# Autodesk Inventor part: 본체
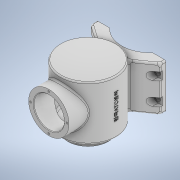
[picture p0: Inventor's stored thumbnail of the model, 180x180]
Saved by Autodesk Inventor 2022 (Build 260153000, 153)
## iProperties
Created: 2023-04
Part Number: 본체
Material: 일반
Document SubType Name: Modeling
Designer: Admin
Density: 1 g/cm^3
Appearance: 기본값
Author: Admin
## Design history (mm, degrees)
sketch "스케치1"
  geometry: L1 (-62, 40)-(62, 40); L2 (62, 40)-(62, -40); L3 (62, -40)-(-62, -40); L4 (-62, -40)-(-62, 40); L5 (-86.8, 0)-(86.8, 0) reference; L6 (0, -56)-(0, 56) reference; 1 further point
  constraints: 8 end point, 2 parallel, 1 horizontal, 1 perpendicular, 2 other
  dimensions: "d0" = 124 distance of L1.start L1.end; "d1" = 80 distance of L3.end L1.start
extrude "돌출1" new body sketch "스케치1" stored distance "d2" = 10; taper "d3" = 0 deg
sketch "스케치2"
  geometry: 1 further point
sketch "스케치3"
  geometry: L1 (40, -5)-(-40, -5) reference; L2 (-40, -5)-(-40, 5) reference; L3 (-133.479, 72)-(264.868, 72); L4 (-60, 72)-(-48, 72); L5 (-48, 72)-(-48, 108); L6 (-48, 108)-(-60, 108); L7 (-60, 108)-(-60, 72); L8 (-48, 72)-(-36, 72); L9 (-36, 122)-(-48, 122); L10 (-48, 122)-(-48, 72); L11 (-36, 72)-(36, 72); L12 (36, 72)-(48.336, 72); L13 (48.336, 72)-(48.336, 122); L14 (48.336, 122)-(36, 122); L15 (0, -30.534)-(0, 148.205) reference; L16 (-36, 122)-(36, 122); A1 r 113 centre (-53, 72) between (60, 72) and (48.336, 122); 3 further points
  constraints: 26 end point, 5 horizontal, 5 parallel, 3 point on line, 2 perpendicular, 2 point on circle, 1 centre point
  dimensions: "d16" = 113 radius of A1; "d17" = 20 distance from line of L2 L4.start; "d18" = 120 horizontal distance of L6.end A1.start; "d19" = 108 horizontal distance of A1.start L9.end; "d21" = 72 diameter of L6.end L3; "d22" = 100 diameter of L9.end L3; "d24" = 100 diameter of L13.end L3; "d28" = 154 diameter of L1 L3
revolve "회전1" sketch "스케치3" stored, may be unused: angle "d25" = 90 deg
node "작업 평면1"
sketch "스케치5"
  geometry: L1 (36, -60)-(-36, -60) reference; L2 (0, -84)-(0, 84) reference; C1 r 36 at (0, 2); 1 further point
  constraints: 1 centre point, 1 point on line
  dimensions: "d109" = 62 distance from line of L1 C1.centre; "d110" = 72 diameter of C1
extrude "돌출2" join sketch "스케치5" stored distance "d31" = 142; taper "d32" = 0 deg
sketch "스케치10"
  geometry: L1 (-85.453, 72)-(94.043, 72); L2 (-40, -5)-(40, -5) reference; L3 (-60, 36)-(-60, 108) reference; L4 (-60, 72)-(-41, 72); L5 (-41, 72)-(-41, 99); L6 (-41, 99)-(-60, 99); L7 (-60, 99)-(-60, 72); L8 (-41, 72)-(44.499, 72); L9 (44.499, 72)-(44.499, 115); L10 (44.499, 115)-(-41, 115); L11 (-41, 115)-(-41, 72); A1 r 113 centre (-53, 72) between (48.336, 22) and (48.336, 122) reference; A2 r 113 centre (-60, 72) between (53, 72) and (44.499, 115); 3 further points
  constraints: 18 end point, 4 parallel, 3 horizontal, 2 perpendicular, 2 point on circle, 2 point on line, 1 centre point, 1 midpoint
  dimensions: "d40" = 77 distance between parallel lines of L2 L1; "d42" = 54 diameter of L6.end L1; "d43" = 86 diameter of L10.end L1; "d45" = 19 distance of L5.end L6.end; "d48" = 226 diameter of A2; "d49" = 7 distance of A1.centre A2.centre
revolve "회전2" sketch "스케치10" stored, may be unused: angle "d50" = 90 deg
sketch "스케치22"
  geometry: C1 r 27 at (0, 0); C2 r 36 at (0, 0) reference; 1 further point
  constraints: 1 centre point, 1 coincident
  dimensions: "d112" = 54 diameter of C1
extrude "돌출8" cut sketch "스케치22" stored distance "d113" = 10; taper "d114" = 0 deg
sketch "스케치23"
  geometry: C1 r 27 at (0, 0) reference; C2 r 36 at (0, 0) reference; 5 further points
  constraints: 1 horizontal alignment, 5 other
  dimensions: "d115" = 32.5 distance of C1.centre point (-32.5, 0); "d118" = 360 deg dimension on C2.centre point (-32.5, 0) (derived)
hole "구멍4" sketch "스케치23" at (-32.5, 0), (0, -32.5), (32.5, 0), (0, 32.5) diameter "d120" = 3.242; stored, may be unused: countersink angle "d124" = 90 deg, drill point angle "d126" = 118 deg; dims "d121" = 8, "d122" = 4, "d123" = 2, "d125" = 10
sketch "스케치13"
  geometry: L1 (0, -102.4)-(0, 75.4) reference; C1 r 27 at (0, 0) reference; C2 r 36 at (0, 0) reference; 5 further points
  constraints: 1 point on line, 5 other
  dimensions: "d66" = 32.5 distance of C1.centre point (0, 32.5); "d69" = 360 deg dimension on C2.centre point (0, 32.5) (derived)
hole "구멍2" sketch "스케치13" at (0, 32.5), (-32.5, 0), (0, -32.5), (32.5, 0) diameter "d71" = 3.242; stored, may be unused: countersink angle "d75" = 90 deg, drill point angle "d77" = 118 deg; dims "d72" = 8, "d73" = 4, "d74" = 2, "d76" = 10
sketch "스케치14"
  geometry: L1 (62, 40)-(-62, 40) reference; L2 (-62, -40)-(62, -40) reference; L3 (-10, 40)-(10, 40); L4 (10, 40)-(10, -40); L5 (10, -40)-(-10, -40); L6 (-10, -40)-(-10, 40); L7 (0, -84)-(0, 84) reference; 1 further point
  constraints: 8 end point, 2 parallel, 2 point on line, 1 horizontal, 1 perpendicular, 1 other
  dimensions: "d78" = 20 distance between parallel lines of L6 L4
extrude "돌출5" join sketch "스케치14" stored distance "d79" = 10; taper "d80" = 0 deg
sketch "스케치15"
  geometry: L1 (-62, 5)-(-10, 5) reference; L2 (-62, 5)-(-26.694, 29.722); L3 (-62, -5)-(-62, 5) reference; 2 further points
  constraints: 2 end point, 2 other
  dimensions: "d81" = 55 deg angle of L3 L2
feature "리브1" sketch "스케치15" dims "d82" = 1, "d83" = 80, "d84" = 0, "d85" = 0, "d86" = 1, "d87" = 1
sketch "스케치16"
  geometry: L1 (124, 0)-(0, 0) reference; L2 (62, -12.727)-(62, 19.916); L3 (0, 10)-(0, 0) reference; L4 (62, 17)-(82.89, 17); L5 (23.5, 0)-(100.5, 0); A1 r 52.096 centre (62, -35.096) between (100.5, 0) and (23.5, 0); 1 further point
  constraints: 6 end point, 3 point on circle, 3 point on line, 1 centre point, 1 collinear, 1 horizontal, 1 symmetric about line, 1 tangent, 1 vertical
  dimensions: "d88" = 77 distance of L5.end L5.start; "d89" = 62 distance between parallel lines of L3 L2; "d90" = 17 distance between parallel lines of L1 L4
extrude "돌출6" cut sketch "스케치16" extent not by distance; stored distance "d91" = 0; taper "d92" = 0 deg
sketch "스케치18"
  geometry: L1 (62, -40)-(62, 40) reference; L2 (62, 40)-(38.5, 40) reference; 3 further points
  constraints: 1 vertical alignment
  dimensions: "d95" = 40 distance of point (54, -20) point (54, 20); "d96" = 8 distance from line of L1 point (54, 20); "d97" = 20 distance from line of L2 point (54, 20)
hole "구멍3" sketch "스케치18" at (54, 20), (54, -20) diameter "d98" = 9; stored, may be unused: countersink angle "d102" = 90 deg, drill point angle "d104" = 0 deg; dims "d99" = 6, "d100" = 4, "d101" = 2, "d103" = 6
sketch "스케치20"
  geometry: L1 (8, 20)-(8, -60) reference; L2 (8, -7)-(0, -7); L3 (8, 7)-(0, 7); L4 (8, 7)-(8, -7); C1 r 4.5 at (0, 0) reference; A1 r 7 centre (0, 0) between (0, 7) and (0, -7); 1 further point
  constraints: 6 end point, 2 horizontal, 2 point on circle, 2 point on line, 2 tangent, 1 centre point, 1 coincident
  dimensions: "d106" = 14 diameter of A1
extrude "돌출7" cut sketch "스케치20" distance "d107" = 20; taper "d108" = 0 deg
node "작업 평면2"
sketch "스케치21"
  geometry: L1 (-60.168, -36)-(-60.168, 36) reference; L2 (39.832, -42.278)-(39.832, -42.278) reference; L3 (39.832, -42.278)-(-40.168, -42.278) reference; L4 (-40.168, -42.278)-(-40.168, -42.278) reference; L5 (-40.168, -42.278)-(39.832, -42.278) reference; L6 (48.168, -50)-(48.168, 50) reference; L7 (-48.168, -50)-(-48.168, 50) reference; L8 (39.832, -77)-(-40.168, -77) reference; 3 further points
  constraints: 1 other
  dimensions: "d127" = 62 distance from line of L1 point (1.832, 0); "d128" = 77 distance from line of L8 point (1.832, 0)
feature "엠보싱1" sketch "스케치21" dims "d0" = 124, "d1" = 80, "d16" = 113, "d17" = 20, "d18" = 120, "d19" = 108, "d21" = 72, "d22" = 100, "d24" = 100, "d28" = 154, "d129" = 0.5, "d130" = 0
fillet "모깎기1" dims "d131" = 3
chamfer "모따기1" distance "d132" = 1; stored, may be unused: second distance "d133" = 2, angle "d134" = 45 deg
fillet "모깎기2" dims "d135" = 3
node "솔리드1"
mirror "미러2"
mirror "미러3"
mirror "미러4"
mirror "미러5"
node "투영된 루프7"
node "투영된 루프10"
node "투영된 루프11"
node "투영된 루프12"
feature "A9D066F2-1C7D-4E18-AEED-F7BC21143FA4" dims "d98" = 9, "d99" = 6, "d100" = 4, "d101" = 2, "d102" = 90 deg, "d103" = 6, "d104" = 0
other parameters: "d29" = 142, "d44" = 113
